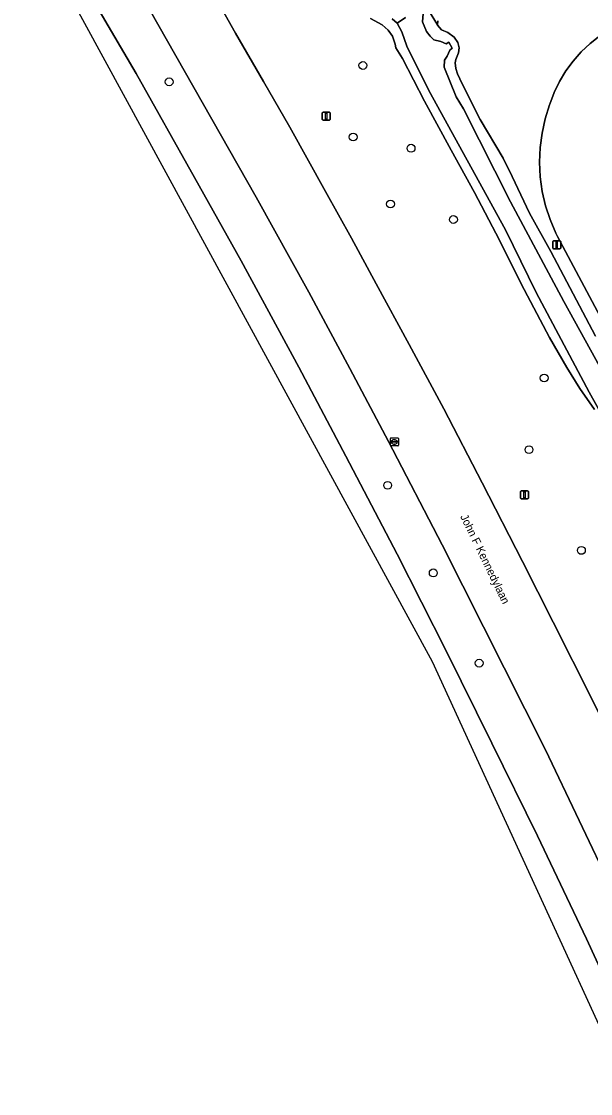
# Model space of a CAD drawing. Extents: x 161385 to 162589, y 388479 to 389756.
# Drawn here: x 161894.9 to 161966, y 388829.4 to 388963.3 of the extents above; entities that cross this region are included whole.
import ezdxf

# ---------------------------------------------------------------- set-up
doc = ezdxf.new("R2010")
doc.units = 0
for name, color, linetype in [('IMGEO_Berm_groen', 7, 'Continuous'), ('IMGEO_Boom', 7, 'Continuous'), ('IMGEO_Kolk', 7, 'Continuous'), ('IMGEO_Lichtmast', 7, 'Continuous'), ('IMGEO_Muur', 7, 'Continuous'), ('IMGEO_Oever', 7, 'Continuous'), ('IMGEO_Openbare_ruimte_label', 7, 'Continuous'), ('IMGEO_Rijbaan_autoweg', 7, 'Continuous'), ('IMGEO_Rijbaan_lokaal_gesloten', 7, 'Continuous'), ('IMGEO_Waterloop', 7, 'Continuous')]:
    doc.layers.add(name, color=color, linetype=linetype)

msp = doc.modelspace()

# ---------------------------------------------------------------- linework, layer by layer
at = {"layer": 'IMGEO_Berm_groen'}
for points in [[(161984.72, 388820.12), (161972.97, 388845.89), (161960.37, 388872.36), (161947.48, 388897.98), (161940.78, 388910.86), (161935.93, 388920.01), (161930.82, 388929.51), (161924.25, 388941.4), (161908.69, 388968.84)], [(161903.1, 388967.38), (161909.25, 388956.84), (161916.53, 388943.85), (161922.36, 388933.43), (161929.58, 388920.15), (161935.46, 388909.04), (161941.86, 388896.82), (161947.92, 388884.82), (161953.68, 388873.19), (161959.37, 388861.6), (161965.51, 388848.76), (161971.55, 388835.65), (161977.44, 388822.72)], [(161918.32, 388967.84), (161921.67, 388961.88), (161925.17, 388955.85), (161928.45, 388950.14), (161932.92, 388942.1), (161936.14, 388936.28), (161939.25, 388930.56), (161943.36, 388922.99), (161947.67, 388914.95), (161952.47, 388905.7), (161957.51, 388895.87), (161961.35, 388888.29), (161966.2, 388878.63), (161970.1, 388870.71), (161973.5, 388863.42), (161976.78, 388856.5), (161981.27, 388846.88), (161984.93, 388838.96), (161989.15, 388829.66), (161993.32, 388820.25)], [(161966.49, 388914.87), (161964.67, 388917.48), (161963.02, 388920.12), (161960.87, 388923.88), (161957.34, 388930.58), (161954.64, 388936.04), (161951.53, 388941.98), (161948.59, 388947.26), (161945.26, 388953.39), (161942.5, 388958.74), (161941.7, 388960.04), (161941.62, 388960.52), (161941.25, 388961.52), (161940.71, 388962.24), (161939.98, 388962.93), (161938.51, 388963.73)], [(161946.95, 388963.44), (161946.9, 388962.91), (161946.9, 388962.89), (161947.4, 388962.3), (161948.2, 388961.95), (161948.98, 388961.39), (161949.44, 388960.71), (161949.59, 388960.04), (161949.52, 388959.43), (161949.17, 388958.61), (161949.08, 388958.16), (161949.17, 388957.46), (161949.38, 388956.8), (161949.99, 388955.56), (161952.22, 388951.1), (161955.08, 388946.26), (161956.23, 388943.96), (161958.36, 388939.39), (161961.04, 388934.61), (161966.61, 388924.05)], [(161995.29, 388873.78), (161961.89, 388936.48), (161961.68, 388936.91), (161960.95, 388938.59), (161960.38, 388940.33), (161959.97, 388942.12), (161959.71, 388943.93), (161959.63, 388945.76), (161959.7, 388947.59), (161959.94, 388949.41), (161960.34, 388951.2), (161960.89, 388952.94), (161960.92, 388953.02), (161961.46, 388954.46), (161962.13, 388955.84), (161962.92, 388957.16), (161963.83, 388958.4), (161964.84, 388959.55), (161965.95, 388960.61), (161967.15, 388961.57)]]:
    msp.add_lwpolyline(points, dxfattribs=at)
at = {"layer": 'IMGEO_Boom'}
for centre in [(161937.57, 388957.85), (161913.38, 388955.8), (161936.36, 388948.91), (161943.59, 388947.51), (161941.02, 388940.54), (161948.88, 388938.6), (161960.21, 388918.81), (161958.32, 388909.85), (161940.66, 388905.4), (161964.86, 388897.27), (161946.36, 388894.46), (161952.09, 388883.19)]:
    msp.add_circle(centre, 0.489, dxfattribs=at)
at = {"layer": 'IMGEO_Kolk'}
for p, q in [((161941, 388910.4), (161941, 388911.25)), ((161941.08, 388911.32), (161941.93, 388911.32)), ((161941.26, 388910.82), (161941.26, 388910.83)), ((161941.7, 388910.78), (161941.3, 388910.78)), ((161941.31, 388910.87), (161941.7, 388910.87)), ((161941.49, 388911.1), (161941.52, 388911.1)), ((161941.75, 388910.83), (161941.75, 388910.82)), ((161942, 388911.25), (161942, 388910.4)), ((161941.93, 388910.32), (161941.08, 388910.32)), ((161941.51, 388910.54), (161941.49, 388910.54))]:
    msp.add_line(p, q, dxfattribs=at)
for points in [[(161941, 388910.4), (161941, 388911.25)], [(161941.08, 388911.32), (161941.93, 388911.32)], [(161942, 388911.25), (161942, 388910.4)], [(161941.93, 388910.32), (161941.08, 388910.32)]]:
    msp.add_lwpolyline(points, dxfattribs=at)
for centre, radius, start, end in [((161941.08, 388911.25), 0.0765, 91.552, 178.448), ((161941.08, 388911.25), 0.0765, 91.552, 178.448), ((161941.3, 388910.83), 0.0403, 85.8775, 175.7526), ((161941.3, 388910.82), 0.0366, 178.938, 274.7102), ((161941.71, 388910.83), 0.0386, 1.7309, 96.639), ((161941.7, 388910.82), 0.043, 264.8664, 352.4533), ((161941.93, 388911.25), 0.0765, 1.552, 88.448), ((161941.93, 388911.25), 0.0765, 1.552, 88.448), ((161941.08, 388910.4), 0.0765, 181.552, 268.448), ((161941.08, 388910.4), 0.0765, 181.552, 268.448), ((161941.93, 388910.4), 0.0765, 271.552, 358.448), ((161941.93, 388910.4), 0.0765, 271.552, 358.448)]:
    msp.add_arc(centre, radius, start, end, dxfattribs=at)
for centre, major_axis, ratio, start_param, end_param in [((161941.49, 388910.82), (-0.387, 0.002), 0.722429, 4.712389, 7.853982), ((161941.51, 388910.82), (-0.39, 0.002), 0.717154, 1.570796, 4.712389)]:
    msp.add_ellipse(centre, major_axis=major_axis, ratio=ratio, start_param=start_param, end_param=end_param, dxfattribs=at)
at = {"layer": 'IMGEO_Lichtmast'}
for p, q in [((161932.5, 388951.12), (161932.5, 388951.92)), ((161932.5, 388951.92), (161932.5, 388951.12)), ((161932.6, 388952.02), (161933.39, 388952.02)), ((161933.39, 388952.02), (161932.6, 388952.02)), ((161933.39, 388951.02), (161932.6, 388951.02)), ((161932.6, 388951.02), (161933.39, 388951.02)), ((161933.49, 388951.92), (161933.49, 388951.12)), ((161933.49, 388951.12), (161933.49, 388951.92)), ((161961.28, 388935.04), (161961.28, 388935.84)), ((161961.28, 388935.84), (161961.28, 388935.04)), ((161961.38, 388935.94), (161962.17, 388935.94)), ((161962.17, 388935.94), (161961.38, 388935.94)), ((161962.17, 388934.94), (161961.38, 388934.94)), ((161961.38, 388934.94), (161962.17, 388934.94)), ((161962.27, 388935.84), (161962.27, 388935.04)), ((161962.27, 388935.04), (161962.27, 388935.84)), ((161957.25, 388903.81), (161957.25, 388904.61)), ((161957.25, 388904.61), (161957.25, 388903.81)), ((161957.35, 388904.71), (161958.14, 388904.71)), ((161958.14, 388904.71), (161957.35, 388904.71)), ((161958.24, 388904.61), (161958.24, 388903.81)), ((161958.24, 388903.81), (161958.24, 388904.61)), ((161958.14, 388903.71), (161957.35, 388903.71)), ((161957.35, 388903.71), (161958.14, 388903.71))]:
    msp.add_line(p, q, dxfattribs=at)
for points in [[(161932.92, 388951.9), (161933.07, 388951.9), (161933.07, 388951.15), (161932.92, 388951.15), (161932.92, 388951.9)], [(161961.7, 388935.82), (161961.85, 388935.82), (161961.85, 388935.07), (161961.7, 388935.07), (161961.7, 388935.82)], [(161957.67, 388904.58), (161957.82, 388904.58), (161957.82, 388903.83), (161957.67, 388903.83), (161957.67, 388904.58)]]:
    msp.add_lwpolyline(points, dxfattribs=at)
for centre, start, end in [((161932.6, 388951.92), 90, 180), ((161932.6, 388951.92), 90, 180), ((161932.6, 388951.12), 180, 270), ((161932.6, 388951.12), 180, 270), ((161933.39, 388951.92), 0, 90), ((161933.39, 388951.92), 360, 90), ((161933.39, 388951.12), 270, 0), ((161933.39, 388951.12), 270, 0), ((161961.38, 388935.84), 90, 180), ((161961.38, 388935.84), 90, 180), ((161961.38, 388935.04), 180, 270), ((161961.38, 388935.04), 180, 270), ((161962.17, 388935.84), 0, 90), ((161962.17, 388935.84), 360, 90), ((161962.17, 388935.04), 270, 0), ((161962.17, 388935.04), 270, 0), ((161957.35, 388904.61), 90, 180), ((161957.35, 388904.61), 90, 180), ((161958.14, 388904.61), 0, 90), ((161958.14, 388904.61), 360, 90), ((161957.35, 388903.81), 180, 270), ((161957.35, 388903.81), 180, 270), ((161958.14, 388903.81), 270, 0), ((161958.14, 388903.81), 270, 0)]:
    msp.add_arc(centre, 0.1, start, end, dxfattribs=at)
at = {"layer": 'IMGEO_Muur'}
for points in [[(161947.99, 388960.56), (161948.32, 388960.76)], [(161948.32, 388960.76), (161948.72, 388960.02)], [(161948.72, 388960.02), (161948.43, 388959.76)]]:
    msp.add_lwpolyline(points, dxfattribs=at)
at = {"layer": 'IMGEO_Oever'}
for points in [[(161945.09, 388964.32), (161945.01, 388963.3), (161945.53, 388962.11), (161945.97, 388961.5), (161946.44, 388961.06), (161947.3, 388960.85), (161947.99, 388960.56), (161948.32, 388960.76), (161948.72, 388960.02), (161948.43, 388959.76), (161948.11, 388958.99), (161947.76, 388958.5), (161947.71, 388957.62), (161949.21, 388953.94), (161950.14, 388952.44), (161956.02, 388940.83), (161962.68, 388928.37), (161970.45, 388914.23)], [(161945.76, 388964.74), (161946.9, 388962.91), (161946.95, 388963.44)], [(161966.61, 388924.05), (161961.04, 388934.61), (161958.36, 388939.39), (161956.23, 388943.96), (161955.08, 388946.26), (161952.22, 388951.1), (161949.99, 388955.56), (161949.38, 388956.8), (161949.17, 388957.46), (161949.08, 388958.16), (161949.17, 388958.61), (161949.52, 388959.43), (161949.59, 388960.04), (161949.44, 388960.71), (161948.98, 388961.39), (161948.2, 388961.95), (161947.4, 388962.3), (161946.9, 388962.89), (161946.9, 388962.91), (161945.76, 388964.74)], [(161938.51, 388963.73), (161939.98, 388962.93), (161940.71, 388962.24), (161941.25, 388961.52), (161941.62, 388960.52), (161941.7, 388960.04), (161942.5, 388958.74), (161945.26, 388953.39), (161948.59, 388947.26), (161951.53, 388941.98), (161954.64, 388936.04), (161957.34, 388930.58), (161960.87, 388923.88), (161963.02, 388920.12), (161964.67, 388917.48), (161966.49, 388914.87)], [(162057.6, 388706.61), (162048.46, 388732.27), (162043.65, 388745.63), (162037.76, 388760.64), (162034.26, 388770.35), (162029.94, 388781.92), (162028.76, 388785.06), (162028.09, 388786.86), (162022.9, 388800), (162017.3, 388813.29), (162011.73, 388825.52), (161997.03, 388856.73), (161992.96, 388865.62), (161985.65, 388880.17), (161979.24, 388892.22), (161973.46, 388903.38), (161965.83, 388917.05), (161959.22, 388929.48), (161955.4, 388937.31), (161945.81, 388954.71), (161943.05, 388960.24), (161942.45, 388962.06), (161941.84, 388963.12), (161941.22, 388963.68)]]:
    msp.add_lwpolyline(points, dxfattribs=at)
at = {"layer": 'IMGEO_Rijbaan_autoweg'}
for points in [[(161894.93, 388977.64), (161946.23, 388883.4), (161982.73, 388803.78), (162002.96, 388756.57), (162004.74, 388756.82), (162005.25, 388756.29), (162003.37, 388761.08), (161998.89, 388772.37), (161994.25, 388783.9), (161988.74, 388797.15), (161983.09, 388810.13), (161977.44, 388822.72), (161971.55, 388835.65), (161965.51, 388848.76), (161959.37, 388861.6), (161953.68, 388873.19), (161947.92, 388884.82), (161941.86, 388896.82), (161935.46, 388909.04), (161929.58, 388920.15), (161922.36, 388933.43), (161916.53, 388943.85), (161909.25, 388956.84), (161903.1, 388967.38)], [(161908.69, 388968.84), (161924.25, 388941.4), (161930.82, 388929.51), (161935.93, 388920.01), (161940.78, 388910.86), (161947.48, 388897.98), (161960.37, 388872.36), (161972.97, 388845.89), (161984.72, 388820.12)], [(161993.32, 388820.25), (161989.15, 388829.66), (161984.93, 388838.96), (161981.27, 388846.88), (161976.78, 388856.5), (161973.5, 388863.42), (161970.1, 388870.71), (161966.2, 388878.63), (161961.35, 388888.29), (161957.51, 388895.87), (161952.47, 388905.7), (161947.67, 388914.95), (161943.36, 388922.99), (161939.25, 388930.56), (161936.14, 388936.28), (161932.92, 388942.1), (161928.45, 388950.14), (161925.17, 388955.85), (161921.67, 388961.88), (161918.32, 388967.84)]]:
    msp.add_lwpolyline(points, dxfattribs=at)
at = {"layer": 'IMGEO_Rijbaan_lokaal_gesloten'}
msp.add_lwpolyline([(161967.15, 388961.57), (161965.95, 388960.61), (161964.84, 388959.55), (161963.83, 388958.4), (161962.92, 388957.16), (161962.13, 388955.84), (161961.46, 388954.46), (161960.92, 388953.02), (161960.89, 388952.94), (161960.34, 388951.2), (161959.94, 388949.41), (161959.7, 388947.59), (161959.63, 388945.76), (161959.71, 388943.93), (161959.97, 388942.12), (161960.38, 388940.33), (161960.95, 388938.59), (161961.68, 388936.91), (161961.89, 388936.48), (161995.29, 388873.78)], dxfattribs=at)
at = {"layer": 'IMGEO_Waterloop'}
for points in [[(161970.45, 388914.23), (161962.68, 388928.37), (161956.02, 388940.83), (161950.14, 388952.44), (161949.21, 388953.94), (161947.71, 388957.62), (161947.76, 388958.5), (161948.11, 388958.99), (161948.43, 388959.76), (161948.72, 388960.02), (161948.32, 388960.76), (161947.99, 388960.56), (161947.3, 388960.85), (161946.44, 388961.06), (161945.97, 388961.5), (161945.53, 388962.11), (161945.01, 388963.3), (161945.09, 388964.32)], [(161941.22, 388963.68), (161941.84, 388963.12), (161942.88, 388963.86)], [(161942.88, 388963.86), (161941.84, 388963.12), (161942.45, 388962.06), (161943.05, 388960.24), (161945.81, 388954.71), (161955.4, 388937.31), (161959.22, 388929.48), (161965.83, 388917.05), (161973.46, 388903.38), (161979.24, 388892.22), (161985.65, 388880.17), (161992.96, 388865.62), (161997.03, 388856.73), (162011.73, 388825.52)]]:
    msp.add_lwpolyline(points, dxfattribs=at)

# ---------------------------------------------------------------- texts
at = {"layer": 'IMGEO_Openbare_ruimte_label'}
msp.add_text('John F Kennedylaan', height=1, rotation=295.9242, dxfattribs=at).set_placement((161949.7, 388901.5))

doc.saveas('drawing.dxf')
